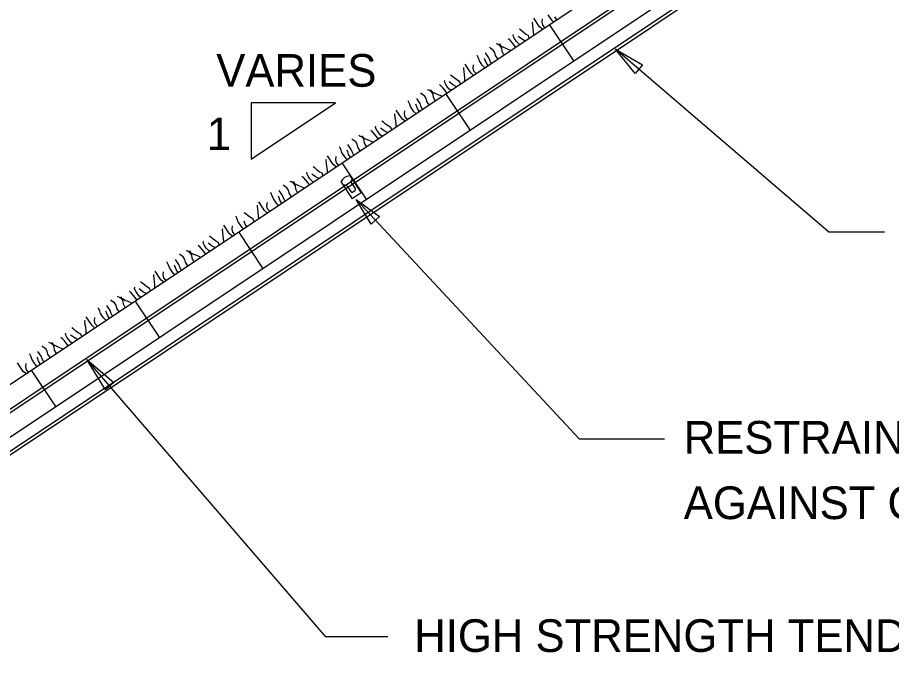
# Model space of a CAD drawing. Extents: x 638850 to 644908, y 297188 to 298900.
# Drawn here: x 642012.2 to 642084.2, y 297529.6 to 297583.4 of the extents above; entities that cross this region are included whole.
import ezdxf

# ---------------------------------------------------------------- set-up
doc = ezdxf.new("R2010")
doc.units = 0
for name, color, linetype in [('3', 7, 'Continuous'), ('4', 7, 'Continuous'), ('5', 7, 'Continuous'), ('6', 7, 'Continuous'), ('7', 7, 'Continuous'), ('8', 7, 'Continuous'), ('9', 7, 'Continuous')]:
    doc.layers.add(name, color=color, linetype=linetype)

msp = doc.modelspace()

# ---------------------------------------------------------------- linework, layer by layer
at = {"layer": '4'}
msp.add_lwpolyline([(642116.422, 297620.757), (641930.366, 297496.673), (641930.211, 297496.907), (642116.267, 297620.99)], close=True, dxfattribs=at)
at = {"layer": '5'}
for p, q in [((641929.742, 297498.589), (642115.798, 297622.673)), ((641930.835, 297494.991), (642116.889, 297619.072)), ((642058.046, 297579.829), (642056.048, 297582.823)), ((642049.51, 297574.135), (642047.512, 297577.131)), ((642040.973, 297568.444), (642038.975, 297571.438)), ((642032.437, 297562.75), (642030.441, 297565.746)), ((642023.903, 297557.058), (642021.905, 297560.052)), ((642015.367, 297551.365), (642013.369, 297554.361))]:
    msp.add_line(p, q, dxfattribs=at)
at = {"layer": '6'}
for p, q in [((642079.065, 297565.705), (642061.478, 297580.797)), ((642038.41, 297576.36), (642031.467, 297576.36)), ((642031.467, 297576.36), (642031.467, 297571.729)), ((642031.467, 297571.729), (642038.41, 297576.36)), ((642058.528, 297548.667), (642040.112, 297568.405)), ((642083.64, 297565.705), (642079.065, 297565.705)), ((642037.623, 297532.402), (642017.922, 297555.233)), ((642065.507, 297548.667), (642058.528, 297548.667)), ((642042.719, 297532.402), (642037.623, 297532.402))]:
    msp.add_line(p, q, dxfattribs=at)
for points in [[(642063.109, 297578.782), (642061.478, 297580.797), (642063.716, 297579.49)], [(642041.364, 297566.385), (642040.112, 297568.405), (642042.045, 297567.022)], [(642019.456, 297552.743), (642017.922, 297555.233), (642020.162, 297553.35)]]:
    msp.add_lwpolyline(points, close=True, dxfattribs=at)
at = {"layer": '7'}
for p, q in [((642039.62, 297570.334), (642040.54, 297568.954)), ((642039.798, 297570.067), (642039.796, 297570.066)), ((642038.871, 297569.835), (642039.792, 297568.455)), ((642039.052, 297569.57), (642039.049, 297569.568)), ((642039.364, 297569.507), (642039.666, 297569.055)), ((642039.734, 297569.754), (642040.036, 297569.302)), ((642040.54, 297568.954), (642039.792, 297568.455)), ((642039.821, 297569.023), (642040.005, 297569.146))]:
    msp.add_line(p, q, dxfattribs=at)
for centre, radius, start, end in [((642039.695, 297569.412), 0.956, 97.75548, 149.64449), ((642039.573, 297570.303), 0.0562, 33.69952, 97.7554), ((642039.921, 297569.879), 0.225, 123.69996, 213.69998), ((642038.919, 297569.866), 0.0562, 149.64414, 213.69998), ((642039.177, 297569.382), 0.225, 33.70002, 123.70004), ((642039.942, 297569.239), 0.112, 303.7, 33.69998), ((642039.76, 297569.117), 0.112, 213.70002, 303.7)]:
    msp.add_arc(centre, radius, start, end, dxfattribs=at)
at = {"layer": '8'}
msp.add_lwpolyline([(642117.502, 297617.992), (641931.585, 297494.002), (641931.429, 297494.233), (642117.347, 297618.225)], close=True, dxfattribs=at)
at = {"layer": '9'}
for p, q in [((642056.175, 297583.255), (642055.932, 297583.62)), ((642054.644, 297582.978), (642054.659, 297583.053)), ((642054.674, 297582.715), (642054.644, 297582.978)), ((642055.227, 297582.622), (642054.753, 297583.332)), ((642055.429, 297583.012), (642055.46, 297583.276)), ((642055.484, 297582.765), (642055.429, 297583.012)), ((642056.326, 297583.083), (642056.175, 297583.255)), ((642056.374, 297583.042), (642056.326, 297583.083)), ((642056.633, 297583.251), (642056.49, 297583.465)), ((642056.655, 297583.229), (642056.633, 297583.251)), ((642053.695, 297582.346), (642053.565, 297582.431)), ((642053.874, 297582.182), (642053.695, 297582.346)), ((642054.074, 297582.035), (642053.874, 297582.182)), ((642054.708, 297582.458), (642054.674, 297582.715)), ((642054.74, 297582.196), (642054.708, 297582.458)), ((642054.748, 297581.958), (642054.74, 297582.196)), ((642055.403, 297582.467), (642055.227, 297582.622)), ((642055.444, 297582.421), (642055.403, 297582.467)), ((642055.639, 297582.588), (642055.484, 297582.765)), ((642055.668, 297582.571), (642055.639, 297582.588)), ((642052.796, 297581.528), (642052.645, 297581.646)), ((642052.947, 297581.356), (642052.796, 297581.528)), ((642053.052, 297581.881), (642053.081, 297582.001)), ((642053.158, 297581.668), (642053.052, 297581.881)), ((642053.304, 297581.449), (642053.158, 297581.668)), ((642053.543, 297581.783), (642053.452, 297581.865)), ((642053.744, 297581.633), (642053.543, 297581.783)), ((642053.969, 297581.511), (642053.744, 297581.633)), ((642054.027, 297581.477), (642053.969, 297581.511)), ((642054.305, 297581.906), (642054.074, 297582.035)), ((642054.374, 297581.708), (642054.305, 297581.906)), ((642051.204, 297580.856), (642051.099, 297580.96)), ((642051.409, 297580.712), (642051.204, 297580.856)), ((642051.756, 297581.188), (642051.656, 297581.23)), ((642051.985, 297581.06), (642051.756, 297581.188)), ((642052.063, 297581.039), (642051.946, 297581.216)), ((642052.114, 297580.866), (642051.985, 297581.06)), ((642052.29, 297580.918), (642052.063, 297581.039)), ((642052.146, 297580.604), (642052.114, 297580.866)), ((642052.526, 297580.821), (642052.29, 297580.918)), ((642052.772, 297580.712), (642052.526, 297580.821)), ((642053.12, 297581.152), (642052.947, 297581.356)), ((642053.249, 297580.958), (642053.12, 297581.152)), ((642053.458, 297581.271), (642053.304, 297581.449)), ((642053.58, 297581.179), (642053.458, 297581.271)), ((642050.098, 297580.256), (642050.065, 297580.306)), ((642050.199, 297580.051), (642050.098, 297580.256)), ((642050.266, 297579.841), (642050.199, 297580.051)), ((642050.757, 297579.896), (642050.703, 297580.031)), ((642051.046, 297580.089), (642050.773, 297580.498)), ((642051.119, 297579.882), (642051.046, 297580.089)), ((642051.538, 297580.518), (642051.409, 297580.712)), ((642051.594, 297580.272), (642051.538, 297580.518)), ((642051.787, 297579.983), (642051.594, 297580.272)), ((642052.263, 297580.373), (642052.146, 297580.604)), ((642052.317, 297580.336), (642052.263, 297580.373)), ((642052.822, 297580.673), (642052.772, 297580.712)), ((642049.561, 297578.843), (642049.087, 297579.553)), ((642049.763, 297579.233), (642049.794, 297579.498)), ((642050.509, 297579.476), (642050.266, 297579.841)), ((642050.66, 297579.304), (642050.509, 297579.476)), ((642050.708, 297579.264), (642050.66, 297579.304)), ((642050.824, 297579.686), (642050.757, 297579.896)), ((642050.967, 297579.472), (642050.824, 297579.686)), ((642050.989, 297579.45), (642050.967, 297579.472)), ((642051.219, 297579.677), (642051.119, 297579.882)), ((642051.26, 297579.631), (642051.219, 297579.677)), ((642048.029, 297578.567), (642047.899, 297578.652)), ((642048.978, 297579.2), (642048.993, 297579.275)), ((642049.008, 297578.937), (642048.978, 297579.2)), ((642049.042, 297578.679), (642049.008, 297578.937)), ((642049.074, 297578.417), (642049.042, 297578.679)), ((642049.737, 297578.688), (642049.561, 297578.843)), ((642049.778, 297578.643), (642049.737, 297578.688)), ((642049.818, 297578.987), (642049.763, 297579.233)), ((642049.973, 297578.809), (642049.818, 297578.987)), ((642050.002, 297578.793), (642049.973, 297578.809)), ((642047.13, 297577.75), (642046.979, 297577.867)), ((642047.386, 297578.102), (642047.415, 297578.222)), ((642047.492, 297577.889), (642047.386, 297578.102)), ((642047.638, 297577.67), (642047.492, 297577.889)), ((642047.877, 297578.004), (642047.786, 297578.086)), ((642048.078, 297577.855), (642047.877, 297578.004)), ((642048.21, 297578.405), (642048.029, 297578.567)), ((642048.303, 297577.732), (642048.078, 297577.855)), ((642048.408, 297578.256), (642048.21, 297578.405)), ((642048.639, 297578.127), (642048.408, 297578.256)), ((642048.708, 297577.93), (642048.639, 297578.127)), ((642049.082, 297578.179), (642049.074, 297578.417)), ((642045.538, 297577.077), (642045.433, 297577.181)), ((642046.09, 297577.409), (642045.99, 297577.451)), ((642046.319, 297577.281), (642046.09, 297577.409)), ((642046.397, 297577.261), (642046.28, 297577.437)), ((642046.448, 297577.087), (642046.319, 297577.281)), ((642046.624, 297577.139), (642046.397, 297577.261)), ((642046.86, 297577.042), (642046.624, 297577.139)), ((642047.281, 297577.578), (642047.13, 297577.75)), ((642047.454, 297577.373), (642047.281, 297577.578)), ((642047.583, 297577.179), (642047.454, 297577.373)), ((642047.792, 297577.493), (642047.638, 297577.67)), ((642047.914, 297577.4), (642047.792, 297577.493)), ((642048.361, 297577.698), (642048.303, 297577.732)), ((642044.432, 297576.477), (642044.399, 297576.528)), ((642044.533, 297576.272), (642044.432, 297576.477)), ((642045.38, 297576.31), (642045.107, 297576.719)), ((642045.743, 297576.933), (642045.538, 297577.077)), ((642045.872, 297576.739), (642045.743, 297576.933)), ((642045.928, 297576.493), (642045.872, 297576.739)), ((642046.121, 297576.204), (642045.928, 297576.493)), ((642046.48, 297576.825), (642046.448, 297577.087)), ((642046.597, 297576.595), (642046.48, 297576.825)), ((642046.653, 297576.559), (642046.597, 297576.595)), ((642047.106, 297576.934), (642046.86, 297577.042)), ((642047.157, 297576.895), (642047.106, 297576.934)), ((642043.895, 297575.065), (642043.421, 297575.774)), ((642044.097, 297575.454), (642044.128, 297575.719)), ((642044.6, 297576.062), (642044.533, 297576.272)), ((642044.843, 297575.697), (642044.6, 297576.062)), ((642044.994, 297575.525), (642044.843, 297575.697)), ((642045.091, 297576.117), (642045.037, 297576.252)), ((642045.158, 297575.907), (642045.091, 297576.117)), ((642045.301, 297575.693), (642045.158, 297575.907)), ((642045.325, 297575.673), (642045.301, 297575.693)), ((642045.453, 297576.104), (642045.38, 297576.31)), ((642045.553, 297575.898), (642045.453, 297576.104)), ((642045.594, 297575.853), (642045.553, 297575.898)), ((642043.312, 297575.421), (642043.327, 297575.496)), ((642043.342, 297575.158), (642043.312, 297575.421)), ((642043.376, 297574.9), (642043.342, 297575.158)), ((642044.071, 297574.909), (642043.895, 297575.065)), ((642044.152, 297575.208), (642044.097, 297575.454)), ((642044.307, 297575.031), (642044.152, 297575.208)), ((642044.336, 297575.014), (642044.307, 297575.031)), ((642045.042, 297575.485), (642044.994, 297575.525)), ((642041.72, 297574.323), (642041.749, 297574.444)), ((642041.826, 297574.111), (642041.72, 297574.323)), ((642042.211, 297574.225), (642042.12, 297574.307)), ((642042.363, 297574.788), (642042.233, 297574.873)), ((642042.544, 297574.626), (642042.363, 297574.788)), ((642042.743, 297574.479), (642042.544, 297574.626)), ((642042.973, 297574.349), (642042.743, 297574.479)), ((642043.042, 297574.151), (642042.973, 297574.349)), ((642043.408, 297574.639), (642043.376, 297574.9)), ((642043.416, 297574.4), (642043.408, 297574.639)), ((642044.112, 297574.864), (642044.071, 297574.909)), ((642040.424, 297573.63), (642040.324, 297573.672)), ((642040.653, 297573.502), (642040.424, 297573.63)), ((642040.731, 297573.482), (642040.614, 297573.658)), ((642041.464, 297573.971), (642041.313, 297574.088)), ((642041.615, 297573.799), (642041.464, 297573.971)), ((642041.788, 297573.595), (642041.615, 297573.799)), ((642041.917, 297573.401), (642041.788, 297573.595)), ((642041.972, 297573.891), (642041.826, 297574.111)), ((642042.126, 297573.714), (642041.972, 297573.891)), ((642042.248, 297573.621), (642042.126, 297573.714)), ((642042.412, 297574.076), (642042.211, 297574.225)), ((642042.637, 297573.953), (642042.412, 297574.076)), ((642042.695, 297573.92), (642042.637, 297573.953)), ((642039.714, 297572.531), (642039.441, 297572.941)), ((642039.872, 297573.298), (642039.767, 297573.402)), ((642040.077, 297573.155), (642039.872, 297573.298)), ((642040.206, 297572.961), (642040.077, 297573.155)), ((642040.262, 297572.714), (642040.206, 297572.961)), ((642040.782, 297573.308), (642040.653, 297573.502)), ((642040.958, 297573.36), (642040.731, 297573.482)), ((642040.814, 297573.046), (642040.782, 297573.308)), ((642040.931, 297572.816), (642040.814, 297573.046)), ((642040.987, 297572.78), (642040.931, 297572.816)), ((642041.194, 297573.263), (642040.958, 297573.36)), ((642041.44, 297573.155), (642041.194, 297573.263)), ((642041.491, 297573.117), (642041.44, 297573.155)), ((642038.766, 297572.699), (642038.733, 297572.749)), ((642038.867, 297572.493), (642038.766, 297572.699)), ((642038.934, 297572.283), (642038.867, 297572.493)), ((642039.177, 297571.919), (642038.934, 297572.283)), ((642039.425, 297572.338), (642039.371, 297572.473)), ((642039.492, 297572.128), (642039.425, 297572.338)), ((642039.635, 297571.915), (642039.492, 297572.128)), ((642039.787, 297572.325), (642039.714, 297572.531)), ((642039.887, 297572.119), (642039.787, 297572.325)), ((642039.928, 297572.074), (642039.887, 297572.119)), ((642040.455, 297572.425), (642040.262, 297572.714)), ((642037.646, 297571.642), (642037.661, 297571.717)), ((642037.676, 297571.379), (642037.646, 297571.642)), ((642037.71, 297571.122), (642037.676, 297571.379)), ((642038.229, 297571.286), (642037.755, 297571.996)), ((642038.431, 297571.675), (642038.464, 297571.941)), ((642038.486, 297571.429), (642038.431, 297571.675)), ((642038.641, 297571.252), (642038.486, 297571.429)), ((642039.328, 297571.747), (642039.177, 297571.919)), ((642039.376, 297571.706), (642039.328, 297571.747)), ((642039.659, 297571.894), (642039.635, 297571.915)), ((642036.054, 297570.544), (642036.083, 297570.665)), ((642036.697, 297571.009), (642036.567, 297571.094)), ((642036.878, 297570.847), (642036.697, 297571.009)), ((642037.077, 297570.7), (642036.878, 297570.847)), ((642037.307, 297570.57), (642037.077, 297570.7)), ((642037.742, 297570.86), (642037.71, 297571.122)), ((642037.75, 297570.621), (642037.742, 297570.86)), ((642038.405, 297571.131), (642038.229, 297571.286)), ((642038.446, 297571.085), (642038.405, 297571.131)), ((642038.67, 297571.235), (642038.641, 297571.252)), ((642035.798, 297570.192), (642035.647, 297570.31)), ((642035.949, 297570.02), (642035.798, 297570.192)), ((642036.122, 297569.816), (642035.949, 297570.02)), ((642036.16, 297570.332), (642036.054, 297570.544)), ((642036.306, 297570.113), (642036.16, 297570.332)), ((642036.46, 297569.935), (642036.306, 297570.113)), ((642036.545, 297570.446), (642036.454, 297570.528)), ((642036.582, 297569.842), (642036.46, 297569.935)), ((642036.746, 297570.297), (642036.545, 297570.446)), ((642036.973, 297570.176), (642036.746, 297570.297)), ((642037.029, 297570.141), (642036.973, 297570.176)), ((642037.376, 297570.372), (642037.307, 297570.57)), ((642034.206, 297569.52), (642034.102, 297569.624)), ((642034.411, 297569.376), (642034.206, 297569.52)), ((642034.54, 297569.182), (642034.411, 297569.376)), ((642034.758, 297569.852), (642034.658, 297569.894)), ((642034.987, 297569.723), (642034.758, 297569.852)), ((642035.065, 297569.703), (642034.948, 297569.879)), ((642035.116, 297569.529), (642034.987, 297569.723)), ((642035.292, 297569.582), (642035.065, 297569.703)), ((642035.148, 297569.268), (642035.116, 297569.529)), ((642035.265, 297569.037), (642035.148, 297569.268)), ((642035.529, 297569.486), (642035.292, 297569.582)), ((642035.774, 297569.376), (642035.529, 297569.486)), ((642035.825, 297569.338), (642035.774, 297569.376)), ((642036.251, 297569.622), (642036.122, 297569.816)), ((642033.1, 297568.92), (642033.067, 297568.97)), ((642033.201, 297568.714), (642033.1, 297568.92)), ((642033.268, 297568.505), (642033.201, 297568.714)), ((642033.511, 297568.14), (642033.268, 297568.505)), ((642033.759, 297568.559), (642033.705, 297568.695)), ((642033.826, 297568.35), (642033.759, 297568.559)), ((642034.048, 297568.752), (642033.775, 297569.162)), ((642034.121, 297568.546), (642034.048, 297568.752)), ((642034.221, 297568.341), (642034.121, 297568.546)), ((642034.596, 297568.936), (642034.54, 297569.182)), ((642034.789, 297568.646), (642034.596, 297568.936)), ((642035.321, 297569.001), (642035.265, 297569.037)), ((642031.98, 297567.863), (642031.995, 297567.938)), ((642032.01, 297567.6), (642031.98, 297567.863)), ((642032.563, 297567.507), (642032.089, 297568.217)), ((642032.765, 297567.897), (642032.798, 297568.163)), ((642032.82, 297567.65), (642032.765, 297567.897)), ((642033.662, 297567.968), (642033.511, 297568.14)), ((642033.71, 297567.927), (642033.662, 297567.968)), ((642033.969, 297568.136), (642033.826, 297568.35)), ((642033.993, 297568.115), (642033.969, 297568.136)), ((642034.262, 297568.295), (642034.221, 297568.341)), ((642030.222, 297566.998), (642030.189, 297567.048)), ((642031.031, 297567.231), (642030.901, 297567.316)), ((642031.212, 297567.068), (642031.031, 297567.231)), ((642031.411, 297566.921), (642031.212, 297567.068)), ((642032.044, 297567.343), (642032.01, 297567.6)), ((642032.076, 297567.081), (642032.044, 297567.343)), ((642032.084, 297566.843), (642032.076, 297567.081)), ((642032.739, 297567.352), (642032.563, 297567.507)), ((642032.78, 297567.306), (642032.739, 297567.352)), ((642032.975, 297567.473), (642032.82, 297567.65)), ((642033.004, 297567.456), (642032.975, 297567.473)), ((642030.323, 297566.792), (642030.222, 297566.998)), ((642030.39, 297566.583), (642030.323, 297566.792)), ((642030.633, 297566.218), (642030.39, 297566.583)), ((642030.948, 297566.428), (642030.881, 297566.637)), ((642031.091, 297566.214), (642030.948, 297566.428)), ((642031.641, 297566.791), (642031.411, 297566.921)), ((642031.71, 297566.593), (642031.641, 297566.791)), ((642029.102, 297565.941), (642029.117, 297566.016)), ((642029.132, 297565.678), (642029.102, 297565.941)), ((642029.166, 297565.421), (642029.132, 297565.678)), ((642029.685, 297565.585), (642029.211, 297566.295)), ((642029.887, 297565.975), (642029.918, 297566.239)), ((642029.942, 297565.728), (642029.887, 297565.975)), ((642030.097, 297565.551), (642029.942, 297565.728)), ((642030.784, 297566.046), (642030.633, 297566.218)), ((642030.832, 297566.005), (642030.784, 297566.046)), ((642031.113, 297566.192), (642031.091, 297566.214)), ((642027.51, 297564.844), (642027.539, 297564.964)), ((642028.153, 297565.309), (642028.023, 297565.394)), ((642028.332, 297565.145), (642028.153, 297565.309)), ((642028.532, 297564.998), (642028.332, 297565.145)), ((642028.763, 297564.869), (642028.532, 297564.998)), ((642029.198, 297565.159), (642029.166, 297565.421)), ((642029.206, 297564.921), (642029.198, 297565.159)), ((642029.861, 297565.43), (642029.685, 297565.585)), ((642029.902, 297565.384), (642029.861, 297565.43)), ((642030.126, 297565.534), (642030.097, 297565.551)), ((642026.214, 297564.151), (642026.114, 297564.193)), ((642026.521, 297564.002), (642026.404, 297564.179)), ((642027.254, 297564.491), (642027.103, 297564.609)), ((642027.405, 297564.319), (642027.254, 297564.491)), ((642027.578, 297564.115), (642027.405, 297564.319)), ((642027.616, 297564.631), (642027.51, 297564.844)), ((642027.762, 297564.412), (642027.616, 297564.631)), ((642027.916, 297564.234), (642027.762, 297564.412)), ((642028.001, 297564.746), (642027.91, 297564.828)), ((642028.038, 297564.142), (642027.916, 297564.234)), ((642028.202, 297564.596), (642028.001, 297564.746)), ((642028.427, 297564.474), (642028.202, 297564.596)), ((642028.485, 297564.44), (642028.427, 297564.474)), ((642028.832, 297564.671), (642028.763, 297564.869)), ((642025.504, 297563.052), (642025.231, 297563.461)), ((642025.662, 297563.819), (642025.557, 297563.923)), ((642025.867, 297563.675), (642025.662, 297563.819)), ((642025.996, 297563.481), (642025.867, 297563.675)), ((642026.052, 297563.235), (642025.996, 297563.481)), ((642026.443, 297564.023), (642026.214, 297564.151)), ((642026.572, 297563.829), (642026.443, 297564.023)), ((642026.748, 297563.881), (642026.521, 297564.002)), ((642026.604, 297563.567), (642026.572, 297563.829)), ((642026.721, 297563.336), (642026.604, 297563.567)), ((642026.984, 297563.784), (642026.748, 297563.881)), ((642027.23, 297563.675), (642026.984, 297563.784)), ((642027.28, 297563.636), (642027.23, 297563.675)), ((642027.707, 297563.921), (642027.578, 297564.115)), ((642024.556, 297563.219), (642024.523, 297563.269)), ((642024.657, 297563.014), (642024.556, 297563.219)), ((642024.724, 297562.804), (642024.657, 297563.014)), ((642024.967, 297562.439), (642024.724, 297562.804)), ((642025.215, 297562.859), (642025.161, 297562.994)), ((642025.282, 297562.649), (642025.215, 297562.859)), ((642025.577, 297562.845), (642025.504, 297563.052)), ((642025.677, 297562.64), (642025.577, 297562.845)), ((642026.245, 297562.946), (642026.052, 297563.235)), ((642026.775, 297563.299), (642026.721, 297563.336)), ((642023.436, 297562.163), (642023.451, 297562.238)), ((642023.466, 297561.9), (642023.436, 297562.163)), ((642024.019, 297561.806), (642023.545, 297562.516)), ((642024.221, 297562.196), (642024.252, 297562.461)), ((642024.276, 297561.95), (642024.221, 297562.196)), ((642025.118, 297562.267), (642024.967, 297562.439)), ((642025.166, 297562.227), (642025.118, 297562.267)), ((642025.425, 297562.435), (642025.282, 297562.649)), ((642025.447, 297562.413), (642025.425, 297562.435)), ((642025.718, 297562.594), (642025.677, 297562.64)), ((642022.487, 297561.53), (642022.357, 297561.615)), ((642022.668, 297561.368), (642022.487, 297561.53)), ((642022.866, 297561.219), (642022.668, 297561.368)), ((642023.5, 297561.642), (642023.466, 297561.9)), ((642023.532, 297561.38), (642023.5, 297561.642)), ((642023.54, 297561.142), (642023.532, 297561.38)), ((642024.195, 297561.651), (642024.019, 297561.806)), ((642024.236, 297561.606), (642024.195, 297561.651)), ((642024.431, 297561.772), (642024.276, 297561.95)), ((642024.46, 297561.756), (642024.431, 297561.772)), ((642021.588, 297560.713), (642021.437, 297560.83)), ((642021.739, 297560.541), (642021.588, 297560.713)), ((642021.844, 297561.065), (642021.873, 297561.185)), ((642021.95, 297560.852), (642021.844, 297561.065)), ((642022.096, 297560.633), (642021.95, 297560.852)), ((642022.25, 297560.456), (642022.096, 297560.633)), ((642022.335, 297560.967), (642022.244, 297561.049)), ((642022.536, 297560.818), (642022.335, 297560.967)), ((642022.761, 297560.695), (642022.536, 297560.818)), ((642022.819, 297560.661), (642022.761, 297560.695)), ((642023.097, 297561.09), (642022.866, 297561.219)), ((642023.166, 297560.893), (642023.097, 297561.09)), ((642019.996, 297560.04), (642019.891, 297560.144)), ((642020.201, 297559.896), (642019.996, 297560.04)), ((642020.33, 297559.702), (642020.201, 297559.896)), ((642020.548, 297560.372), (642020.448, 297560.414)), ((642020.777, 297560.244), (642020.548, 297560.372)), ((642020.855, 297560.224), (642020.738, 297560.4)), ((642020.906, 297560.05), (642020.777, 297560.244)), ((642021.082, 297560.102), (642020.855, 297560.224)), ((642020.938, 297559.788), (642020.906, 297560.05)), ((642021.318, 297560.005), (642021.082, 297560.102)), ((642021.564, 297559.897), (642021.318, 297560.005)), ((642021.615, 297559.858), (642021.564, 297559.897)), ((642021.912, 297560.336), (642021.739, 297560.541)), ((642022.041, 297560.142), (642021.912, 297560.336)), ((642022.372, 297560.363), (642022.25, 297560.456)), ((642018.89, 297559.44), (642018.857, 297559.491)), ((642018.991, 297559.235), (642018.89, 297559.44)), ((642019.058, 297559.025), (642018.991, 297559.235)), ((642019.549, 297559.08), (642019.495, 297559.215)), ((642019.838, 297559.273), (642019.565, 297559.682)), ((642019.911, 297559.067), (642019.838, 297559.273)), ((642020.386, 297559.456), (642020.33, 297559.702)), ((642020.579, 297559.167), (642020.386, 297559.456)), ((642021.055, 297559.558), (642020.938, 297559.788)), ((642021.111, 297559.522), (642021.055, 297559.558)), ((642017.77, 297558.384), (642017.785, 297558.459)), ((642018.353, 297558.028), (642017.879, 297558.737)), ((642018.555, 297558.417), (642018.586, 297558.682)), ((642018.61, 297558.171), (642018.555, 297558.417)), ((642019.301, 297558.66), (642019.058, 297559.025)), ((642019.452, 297558.488), (642019.301, 297558.66)), ((642019.5, 297558.448), (642019.452, 297558.488)), ((642019.616, 297558.87), (642019.549, 297559.08)), ((642019.759, 297558.656), (642019.616, 297558.87)), ((642019.783, 297558.636), (642019.759, 297558.656)), ((642020.011, 297558.861), (642019.911, 297559.067)), ((642020.052, 297558.816), (642020.011, 297558.861)), ((642016.821, 297557.751), (642016.691, 297557.836)), ((642017.002, 297557.589), (642016.821, 297557.751)), ((642017.8, 297558.121), (642017.77, 297558.384)), ((642017.834, 297557.863), (642017.8, 297558.121)), ((642017.866, 297557.602), (642017.834, 297557.863)), ((642018.529, 297557.872), (642018.353, 297558.028)), ((642018.57, 297557.827), (642018.529, 297557.872)), ((642018.765, 297557.994), (642018.61, 297558.171)), ((642018.794, 297557.977), (642018.765, 297557.994)), ((642015.922, 297556.934), (642015.771, 297557.051)), ((642016.178, 297557.286), (642016.207, 297557.407)), ((642016.284, 297557.074), (642016.178, 297557.286)), ((642016.43, 297556.854), (642016.284, 297557.074)), ((642016.669, 297557.188), (642016.578, 297557.27)), ((642016.87, 297557.039), (642016.669, 297557.188)), ((642017.095, 297556.916), (642016.87, 297557.039)), ((642017.201, 297557.442), (642017.002, 297557.589)), ((642017.431, 297557.312), (642017.201, 297557.442)), ((642017.5, 297557.114), (642017.431, 297557.312)), ((642017.874, 297557.363), (642017.866, 297557.602)), ((642014.33, 297556.261), (642014.225, 297556.365)), ((642014.535, 297556.118), (642014.33, 297556.261)), ((642014.882, 297556.593), (642014.782, 297556.635)), ((642015.111, 297556.465), (642014.882, 297556.593)), ((642015.189, 297556.445), (642015.072, 297556.621)), ((642015.24, 297556.271), (642015.111, 297556.465)), ((642015.416, 297556.323), (642015.189, 297556.445)), ((642015.272, 297556.009), (642015.24, 297556.271)), ((642015.652, 297556.226), (642015.416, 297556.323)), ((642016.073, 297556.762), (642015.922, 297556.934)), ((642016.246, 297556.558), (642016.073, 297556.762)), ((642016.375, 297556.364), (642016.246, 297556.558)), ((642016.584, 297556.677), (642016.43, 297556.854)), ((642016.706, 297556.584), (642016.584, 297556.677)), ((642017.153, 297556.883), (642017.095, 297556.916)), ((642013.224, 297555.662), (642013.191, 297555.712)), ((642013.325, 297555.456), (642013.224, 297555.662)), ((642014.172, 297555.494), (642013.899, 297555.904)), ((642014.664, 297555.924), (642014.535, 297556.118)), ((642014.72, 297555.677), (642014.664, 297555.924)), ((642014.913, 297555.388), (642014.72, 297555.677)), ((642015.389, 297555.779), (642015.272, 297556.009)), ((642015.445, 297555.743), (642015.389, 297555.779)), ((642015.898, 297556.118), (642015.652, 297556.226)), ((642015.949, 297556.08), (642015.898, 297556.118)), ((642012.687, 297554.249), (642012.213, 297554.959)), ((642012.889, 297554.638), (642012.922, 297554.904)), ((642013.392, 297555.246), (642013.325, 297555.456)), ((642013.635, 297554.882), (642013.392, 297555.246)), ((642013.786, 297554.71), (642013.635, 297554.882)), ((642013.883, 297555.301), (642013.829, 297555.436)), ((642013.95, 297555.091), (642013.883, 297555.301)), ((642014.093, 297554.878), (642013.95, 297555.091)), ((642014.117, 297554.857), (642014.093, 297554.878)), ((642014.245, 297555.288), (642014.172, 297555.494)), ((642014.345, 297555.082), (642014.245, 297555.288)), ((642014.386, 297555.037), (642014.345, 297555.082)), ((642012.863, 297554.094), (642012.687, 297554.249)), ((642012.904, 297554.048), (642012.863, 297554.094)), ((642012.944, 297554.392), (642012.889, 297554.638)), ((642013.099, 297554.215), (642012.944, 297554.392)), ((642013.128, 297554.198), (642013.099, 297554.215)), ((642013.834, 297554.669), (642013.786, 297554.71))]:
    msp.add_line(p, q, dxfattribs=at)

# ---------------------------------------------------------------- texts
at = {"layer": '3'}
for s, height, p in [('VARIES', 2.6906, (642028.587, 297577.695)), ('1', 2.679, (642027.809, 297572.477)), ('RESTRAINT CLIPS TIED TO TENDONS AND BEARING', 2.69064, (642067.103, 297547.48)), ('AGAINST CELL WALLS', 2.69064, (642067.103, 297542.089)), ('HIGH STRENGTH TENDONS WHERE INDICATED', 2.6892, (642044.9, 297531.147))]:
    msp.add_text(s, height=height, dxfattribs=at).set_placement(p)

doc.saveas('drawing.dxf')
